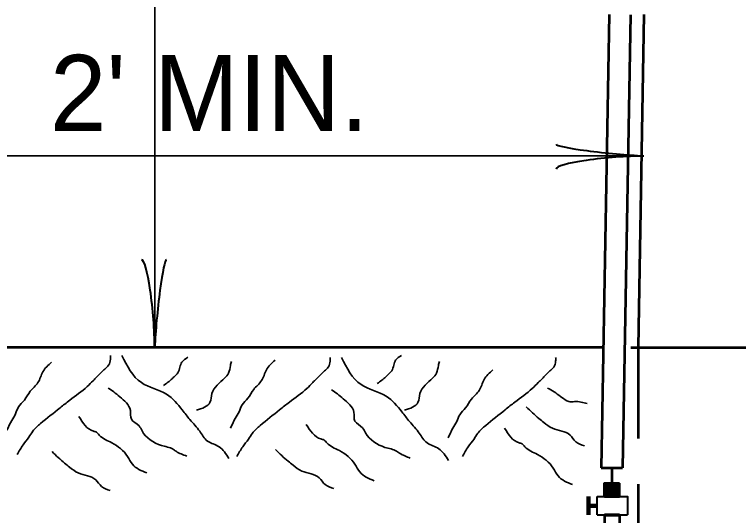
# Model space of a CAD drawing. Extents: x 12366 to 13046, y 9129 to 9570.
# Drawn here: x 12629.98 to 12653.81, y 9391.65 to 9408.13 of the extents above; entities that cross this region are included whole.
import ezdxf
from ezdxf.enums import TextEntityAlignment as Align

# ---------------------------------------------------------------- set-up
doc = ezdxf.new("R2010")
doc.units = 0
doc.linetypes.add('MEDIUM_DASHED', pattern=[4.5, 3, -1.5])
doc.layers.add('1', color=7, linetype='Continuous', lineweight=53)

msp = doc.modelspace()

# ---------------------------------------------------------------- linework, layer by layer
at = {"layer": '1'}
for p, q in [((12649.549, 9408.13), (12649.288, 9393.214)), ((12650.249, 9408.123), (12649.988, 9393.214)), ((12650.692, 9408.13), (12650.501, 9397.186)), ((12650.265, 9397.181), (12672.765, 9397.181)), ((12649.288, 9393.214), (12649.988, 9393.214)), ((12649.638, 9393.214), (12649.638, 9392.714)), ((12649.393, 9392.711), (12649.893, 9392.711)), ((12649.393, 9392.708), (12649.893, 9392.708)), ((12649.393, 9392.702), (12649.893, 9392.702)), ((12649.393, 9392.699), (12649.893, 9392.699)), ((12649.393, 9392.692), (12649.893, 9392.692)), ((12649.393, 9392.688), (12649.893, 9392.688)), ((12649.893, 9392.273), (12649.893, 9392.718)), ((12649.393, 9392.68), (12649.893, 9392.68)), ((12649.393, 9392.677), (12649.893, 9392.677)), ((12649.393, 9392.669), (12649.893, 9392.669)), ((12649.393, 9392.666), (12649.893, 9392.666)), ((12649.393, 9392.659), (12649.893, 9392.659)), ((12649.393, 9392.655), (12649.893, 9392.655)), ((12649.393, 9392.648), (12649.893, 9392.648)), ((12649.393, 9392.644), (12649.893, 9392.644)), ((12649.393, 9392.637), (12649.893, 9392.637)), ((12649.393, 9392.633), (12649.893, 9392.633)), ((12649.393, 9392.628), (12649.893, 9392.628)), ((12649.393, 9392.622), (12649.893, 9392.622)), ((12649.393, 9392.614), (12649.893, 9392.614)), ((12649.393, 9392.611), (12649.893, 9392.611)), ((12649.393, 9392.604), (12649.893, 9392.604)), ((12649.393, 9392.598), (12649.893, 9392.598)), ((12649.393, 9392.59), (12649.893, 9392.59)), ((12649.393, 9392.587), (12649.893, 9392.587)), ((12649.393, 9392.584), (12649.893, 9392.584)), ((12649.393, 9392.579), (12649.893, 9392.579)), ((12649.393, 9392.573), (12649.893, 9392.573)), ((12649.393, 9392.567), (12649.893, 9392.567)), ((12649.393, 9392.562), (12649.893, 9392.562)), ((12649.393, 9392.56), (12649.893, 9392.56)), ((12649.393, 9392.554), (12649.893, 9392.554)), ((12649.393, 9392.551), (12649.893, 9392.551)), ((12649.393, 9392.548), (12649.893, 9392.548)), ((12649.393, 9392.54), (12649.893, 9392.54)), ((12649.393, 9392.537), (12649.893, 9392.537)), ((12649.393, 9392.529), (12649.893, 9392.529)), ((12649.393, 9392.524), (12649.893, 9392.524)), ((12649.393, 9392.518), (12649.893, 9392.518)), ((12649.393, 9392.513), (12649.893, 9392.513)), ((12649.393, 9392.51), (12649.893, 9392.51)), ((12649.393, 9392.504), (12649.893, 9392.504)), ((12649.393, 9392.497), (12649.893, 9392.497)), ((12649.393, 9392.493), (12649.893, 9392.493)), ((12649.393, 9392.486), (12649.893, 9392.486)), ((12649.393, 9392.479), (12649.893, 9392.479)), ((12649.393, 9392.476), (12649.893, 9392.476)), ((12649.393, 9392.471), (12649.893, 9392.471)), ((12649.393, 9392.463), (12649.893, 9392.463)), ((12649.393, 9392.458), (12649.893, 9392.458)), ((12649.393, 9392.453), (12649.893, 9392.453)), ((12649.393, 9392.447), (12649.893, 9392.447)), ((12649.393, 9392.442), (12649.893, 9392.442)), ((12649.393, 9392.435), (12649.893, 9392.435)), ((12649.393, 9392.428), (12649.893, 9392.428)), ((12649.393, 9392.424), (12649.893, 9392.424)), ((12649.393, 9392.417), (12649.893, 9392.417)), ((12649.393, 9392.409), (12649.893, 9392.409)), ((12649.393, 9392.403), (12649.893, 9392.403)), ((12649.393, 9392.397), (12649.893, 9392.397)), ((12649.393, 9392.391), (12649.893, 9392.391)), ((12649.393, 9392.383), (12649.893, 9392.383)), ((12649.393, 9392.378), (12649.893, 9392.378)), ((12649.393, 9392.373), (12649.893, 9392.373)), ((12649.393, 9392.369), (12649.893, 9392.369)), ((12649.393, 9392.364), (12649.893, 9392.364)), ((12649.393, 9392.358), (12649.893, 9392.358)), ((12649.393, 9392.354), (12649.893, 9392.354)), ((12649.393, 9392.35), (12649.893, 9392.35)), ((12649.393, 9392.345), (12649.893, 9392.345)), ((12649.393, 9392.337), (12649.893, 9392.337)), ((12649.393, 9392.331), (12649.893, 9392.331)), ((12649.393, 9392.325), (12649.893, 9392.325)), ((12649.393, 9392.32), (12649.893, 9392.32)), ((12649.393, 9392.312), (12649.893, 9392.312)), ((12649.393, 9392.307), (12649.893, 9392.307)), ((12649.393, 9392.303), (12649.893, 9392.303)), ((12649.393, 9392.295), (12649.893, 9392.295)), ((12649.393, 9392.287), (12649.893, 9392.287)), ((12649.393, 9392.279), (12649.893, 9392.279)), ((12649.393, 9392.274), (12649.893, 9392.274)), ((12649.393, 9391.673), (12649.393, 9369.718)), ((12649.893, 9391.667), (12649.393, 9391.667)), ((12649.893, 9391.663), (12649.393, 9391.663)), ((12649.893, 9391.657), (12649.393, 9391.657)), ((12649.893, 9391.654), (12649.393, 9391.654)), ((12649.893, 9391.673), (12649.893, 9369.718))]:
    msp.add_line(p, q, dxfattribs=at)
at = {"layer": '1', "lineweight": 35}
msp.add_line((12620.321, 9403.479), (12650.681, 9403.479), dxfattribs=at)
at = {"layer": '1', "linetype": 'MEDIUM_DASHED'}
msp.add_line((12650.501, 9397.186), (12650.501, 9376.186), dxfattribs=at)
at = {"layer": '1', "lineweight": 106}
for p, q in [((12648.867, 9391.673), (12648.867, 9392.273)), ((12648.867, 9391.972), (12649.158, 9391.972))]:
    msp.add_line(p, q, dxfattribs=at)
at = {"layer": '1', "lineweight": 40}
for q in [(12649.158, 9392.273), (12650.158, 9391.673)]:
    msp.add_line((12649.158, 9391.673), q, dxfattribs=at)
at = {"layer": '1', "lineweight": 35}
msp.add_lwpolyline([(12634.59, 9449.28), (12634.59, 9434.28), (12634.59, 9397.186)], dxfattribs=at)
at = {"layer": '1'}
for points in [[(12495.321, 9394.186), (12620.321, 9394.186), (12620.321, 9397.186), (12649.358, 9397.186)], [(12649.393, 9392.273), (12649.393, 9392.718), (12649.893, 9392.718)]]:
    msp.add_lwpolyline(points, dxfattribs=at)
at = {"layer": '1', "lineweight": 40}
msp.add_lwpolyline([(12649.158, 9392.273), (12650.158, 9392.273), (12650.158, 9391.673)], dxfattribs=at)
for centre, major_axis, ratio, start_param, end_param in [((12649.56, 9403.691), (1.756, -0.176), 0.07063, 3.140715, 5.41811), ((12649.589, 9403.203), (1.786, 0.156), 0.122415, 0.896353, 3.141593), ((12634.314, 9398.277), (0.156, -1.786), 0.122415, 0.896353, 3.141593), ((12634.802, 9398.307), (0.176, 1.756), 0.07063, 6.282307, 8.559703)]:
    msp.add_ellipse(centre, major_axis=major_axis, ratio=ratio, start_param=start_param, end_param=end_param, dxfattribs=at)
at = {"layer": '1', "lineweight": 35}
for points in [[(12633.137, 9396.917), (12633.137, 9396.789), (12633.073, 9396.597), (12632.945, 9396.469), (12632.817, 9396.341), (12632.561, 9396.085), (12632.369, 9395.893), (12631.793, 9395.445), (12631.474, 9395.189), (12630.834, 9394.677), (12630.578, 9394.421), (12630.45, 9394.229), (12630.258, 9393.974), (12630.066, 9393.654)], [(12633.513, 9396.916), (12634.152, 9396.021), (12634.984, 9395.637), (12635.496, 9395.125), (12635.752, 9394.805), (12636.072, 9394.421), (12636.328, 9394.101), (12636.711, 9393.91), (12637.031, 9393.526)], [(12635.677, 9396.855), (12635.485, 9396.695), (12635.421, 9396.535), (12635.357, 9396.343), (12635.229, 9396.215), (12635.165, 9396.151), (12634.877, 9395.927)], [(12638.554, 9396.759), (12638.266, 9396.439), (12638.106, 9396.087), (12637.85, 9395.799), (12637.658, 9395.511), (12637.466, 9395.287), (12637.37, 9395.063), (12637.243, 9394.839), (12637.083, 9394.52)], [(12640.367, 9396.853), (12640.367, 9396.725), (12640.303, 9396.533), (12640.175, 9396.405), (12640.047, 9396.277), (12639.791, 9396.021), (12639.599, 9395.829), (12639.023, 9395.381), (12638.703, 9395.125), (12638.063, 9394.613), (12637.807, 9394.357), (12637.68, 9394.165), (12637.488, 9393.91), (12637.296, 9393.59)], [(12640.742, 9396.852), (12641.382, 9395.957), (12642.214, 9395.573), (12642.725, 9395.061), (12642.981, 9394.741), (12643.301, 9394.357), (12643.557, 9394.038), (12643.941, 9393.846), (12644.261, 9393.462)], [(12642.714, 9396.919), (12642.522, 9396.759), (12642.458, 9396.599), (12642.395, 9396.407), (12642.267, 9396.279), (12642.203, 9396.215), (12641.915, 9395.991)], [(12647.788, 9396.853), (12647.788, 9396.725), (12647.724, 9396.533), (12647.596, 9396.405), (12647.468, 9396.277), (12647.212, 9396.021), (12647.02, 9395.829), (12646.444, 9395.381), (12646.125, 9395.125), (12645.485, 9394.613), (12645.229, 9394.357), (12645.101, 9394.165), (12644.909, 9393.91), (12644.717, 9393.59)], [(12631.197, 9396.695), (12630.909, 9396.375), (12630.749, 9396.023), (12630.493, 9395.735), (12630.301, 9395.447), (12630.109, 9395.223), (12630.013, 9394.999), (12629.885, 9394.775), (12629.725, 9394.456)], [(12635.963, 9395.117), (12636.411, 9395.373), (12636.475, 9395.661), (12636.891, 9396.173), (12637.019, 9396.333), (12637.083, 9396.588), (12637.115, 9396.716)], [(12642.809, 9395.117), (12643.257, 9395.373), (12643.321, 9395.661), (12643.737, 9396.173), (12643.865, 9396.333), (12643.929, 9396.588), (12643.961, 9396.716)], [(12645.72, 9396.439), (12645.432, 9396.119), (12645.272, 9395.767), (12645.016, 9395.479), (12644.824, 9395.191), (12644.632, 9394.967), (12644.536, 9394.743), (12644.408, 9394.52), (12644.248, 9394.2)], [(12633.054, 9395.843), (12633.246, 9395.715), (12633.438, 9395.555), (12633.79, 9395.108), (12633.822, 9394.82), (12634.078, 9394.596), (12634.173, 9394.436), (12634.813, 9393.956), (12635.197, 9393.828), (12635.293, 9393.764), (12635.645, 9393.604)], [(12647.515, 9395.843), (12647.739, 9395.715), (12648.155, 9395.427), (12648.219, 9395.396), (12648.411, 9395.396), (12648.826, 9395.332)], [(12640.411, 9395.779), (12640.603, 9395.651), (12640.795, 9395.492), (12641.147, 9395.044), (12641.179, 9394.756), (12641.435, 9394.532), (12641.531, 9394.372), (12642.171, 9393.892), (12642.555, 9393.764), (12642.651, 9393.7), (12643.002, 9393.54)], [(12646.822, 9395.225), (12647.238, 9394.841), (12647.398, 9394.713), (12647.685, 9394.521), (12648.261, 9394.298), (12648.453, 9394.074), (12648.741, 9393.946)], [(12632.096, 9394.905), (12632.575, 9394.425), (12632.671, 9394.393), (12632.767, 9394.297), (12633.183, 9394.041), (12633.695, 9393.593), (12633.855, 9393.337), (12634.335, 9393.049)], [(12639.581, 9394.649), (12640.061, 9394.169), (12640.157, 9394.137), (12640.253, 9394.041), (12640.669, 9393.785), (12641.181, 9393.337), (12641.341, 9393.082), (12641.82, 9392.794)], [(12646.107, 9394.521), (12646.587, 9394.041), (12646.683, 9394.009), (12646.779, 9393.913), (12647.195, 9393.657), (12647.706, 9393.209), (12647.866, 9392.953), (12648.346, 9392.666)], [(12631.211, 9393.754), (12631.627, 9393.37), (12631.787, 9393.242), (12632.075, 9393.05), (12632.651, 9392.826), (12632.842, 9392.602), (12633.13, 9392.474)], [(12638.569, 9393.818), (12638.984, 9393.434), (12639.144, 9393.306), (12639.432, 9393.114), (12640.008, 9392.89), (12640.2, 9392.666), (12640.488, 9392.538)]]:
    msp.add_spline(points, degree=3, dxfattribs=at)

# ---------------------------------------------------------------- texts
at = {"layer": '1'}
msp.add_text("2' MIN.", height=2.5, dxfattribs=at).set_placement((12636.385, 9404.302), align=Align.CENTER)

doc.saveas('drawing.dxf')
